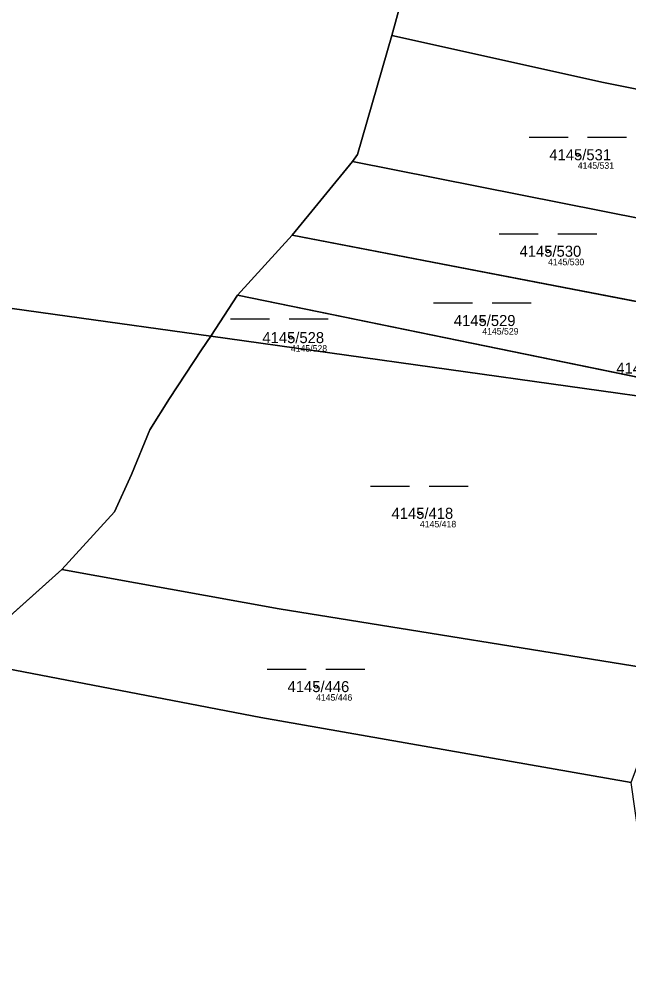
# Model space of a CAD drawing. Extents: x -739214 to -733252, y -1147612 to -1142842.
# Drawn here: x -736257.4 to -736163.6, y -1146792.7 to -1146646.4 of the extents above; entities that cross this region are included whole.
import ezdxf

# ---------------------------------------------------------------- set-up
doc = ezdxf.new("R2010")
doc.units = 0
for name, color, linetype in [('Definiční body', 7, 'Continuous'), ('Hranice parcel', 7, 'Continuous'), ('Parcelní čísla', 7, 'Continuous'), ('Polygon parcely', 7, 'Continuous'), ('Značky kultur', 7, 'Continuous')]:
    doc.layers.add(name, color=color, linetype=linetype)

msp = doc.modelspace()

# ---------------------------------------------------------------- linework, layer by layer
at = {"layer": 'Definiční body'}
for centre in [(-736171.51, -1146667.31), (-736176.09, -1146682.15), (-736186.19, -1146692.81), (-736215.61, -1146695.44), (-736195.77, -1146722.47), (-736211.74, -1146749.13)]:
    msp.add_circle(centre, 0.25, dxfattribs=at)
at = {"layer": 'Hranice parcel'}
for p, q in [((-736250, -1146692.16), (-736446.12, -1146664.77)), ((-736206.12, -1146668.34), (-736215.38, -1146679.7)), ((-736141.82, -1146681.14), (-736206.12, -1146668.34)), ((-736215.38, -1146679.7), (-736223.78, -1146688.92)), ((-736147.96, -1146692.69), (-736215.38, -1146679.7)), ((-736223.78, -1146688.92), (-736227.9, -1146695.24)), ((-736153.6, -1146703.3), (-736223.78, -1146688.92)), ((-736227.9, -1146695.24), (-736250, -1146692.16)), ((-736154.75, -1146705.46), (-736227.9, -1146695.24)), ((-736250.78, -1146731.12), (-736266.33, -1146745))]:
    msp.add_line(p, q, dxfattribs=at)
for points in [[(-736191.94, -1146599.24), (-736191.82, -1146602.51), (-736191.51, -1146612.78), (-736194.36, -1146627.44), (-736196.17, -1146634.72), (-736200.09, -1146648.96)], [(-736200.09, -1146648.96), (-736205.38, -1146667.25), (-736206.12, -1146668.34)], [(-736200.09, -1146648.96), (-736167.56, -1146656.18), (-736132.29, -1146663.24)], [(-736227.9, -1146695.24), (-736229.34, -1146697.34), (-736234.27, -1146704.81), (-736237.3, -1146709.65), (-736240.08, -1146716.48), (-736242.73, -1146722.26), (-736250.78, -1146731.12)], [(-736250.78, -1146731.12), (-736217.41, -1146737.18), (-736156.98, -1146746.9)], [(-736163.29, -1146763.86), (-736220.22, -1146753.87), (-736266.33, -1146745)]]:
    msp.add_lwpolyline(points, dxfattribs=at)
at = {"layer": 'Polygon parcely'}
for points in [[(-736446.12, -1146664.77), (-736250, -1146692.16), (-736227.9, -1146695.24), (-736223.78, -1146688.92), (-736215.38, -1146679.7), (-736206.12, -1146668.34), (-736205.38, -1146667.25), (-736200.09, -1146648.96), (-736196.17, -1146634.72), (-736194.36, -1146627.44), (-736191.51, -1146612.78), (-736191.82, -1146602.51), (-736191.94, -1146599.24), (-736191.78, -1146595.93), (-736191.97, -1146581.49), (-736191.26, -1146573.01), (-736216.79, -1146536.45)], [(-735989.23, -1146792.72), (-736114.21, -1146771.7), (-736117, -1146774.94), (-736127.17, -1146781.53), (-736150.15, -1146782.44), (-736162.08, -1146772.58), (-736163.29, -1146763.86), (-736220.22, -1146753.87), (-736266.33, -1146745)]]:
    msp.add_lwpolyline(points, dxfattribs=at)
for points in [[(-736191.51, -1146612.78), (-736194.36, -1146627.44), (-736196.17, -1146634.72), (-736200.09, -1146648.96), (-736167.56, -1146656.18), (-736132.29, -1146663.24), (-736131.9, -1146662.5), (-736122.58, -1146659.16), (-736112.56, -1146653.29), (-736102.54, -1146647.43), (-736083.6, -1146636.35), (-736081.11, -1146634.89), (-736082.04, -1146628.49), (-736082.68, -1146624.08), (-736191.94, -1146599.24), (-736191.82, -1146602.51)], [(-736206.12, -1146668.34), (-736141.82, -1146681.14), (-736132.29, -1146663.24), (-736167.56, -1146656.18), (-736200.09, -1146648.96), (-736205.38, -1146667.25)], [(-736266.33, -1146745), (-736250.78, -1146731.12), (-736242.73, -1146722.26), (-736240.08, -1146716.48), (-736237.3, -1146709.65), (-736234.27, -1146704.81), (-736229.34, -1146697.34), (-736227.9, -1146695.24), (-736250, -1146692.16), (-736446.12, -1146664.77), (-736393.74, -1146686.21), (-736368.55, -1146706.39), (-736342.55, -1146711.96), (-736320.63, -1146726.6), (-736322.44, -1146734.9), (-736298.37, -1146731.88), (-736275.71, -1146735.8)], [(-736215.38, -1146679.7), (-736147.96, -1146692.69), (-736141.82, -1146681.14), (-736206.12, -1146668.34)], [(-736147.96, -1146692.69), (-736215.38, -1146679.7), (-736223.78, -1146688.92), (-736153.6, -1146703.3)], [(-736223.78, -1146688.92), (-736227.9, -1146695.24), (-736154.75, -1146705.46), (-736153.6, -1146703.3)], [(-736242.73, -1146722.26), (-736250.78, -1146731.12), (-736217.41, -1146737.18), (-736156.98, -1146746.9), (-736156.2, -1146744.79), (-736157.02, -1146732.09), (-736157.82, -1146719.87), (-736157.9, -1146718.62), (-736156.13, -1146711.23), (-736154.75, -1146705.46), (-736227.9, -1146695.24), (-736229.34, -1146697.34), (-736234.27, -1146704.81), (-736237.3, -1146709.65), (-736240.08, -1146716.48)], [(-736266.33, -1146745), (-736220.22, -1146753.87), (-736163.29, -1146763.86), (-736156.98, -1146746.9), (-736217.41, -1146737.18), (-736250.78, -1146731.12)]]:
    msp.add_lwpolyline(points, close=True, dxfattribs=at)
at = {"layer": 'Značky kultur'}
for p, q in [((-736179, -1146664.61), (-736173, -1146664.61)), ((-736170, -1146664.61), (-736164, -1146664.61)), ((-736183.58, -1146679.45), (-736177.58, -1146679.45)), ((-736174.58, -1146679.45), (-736168.58, -1146679.45)), ((-736193.68, -1146690.11), (-736187.68, -1146690.11)), ((-736184.68, -1146690.11), (-736178.68, -1146690.11)), ((-736224.88, -1146692.54), (-736218.88, -1146692.54)), ((-736215.88, -1146692.54), (-736209.88, -1146692.54)), ((-736203.37, -1146718.29), (-736197.37, -1146718.29)), ((-736194.37, -1146718.29), (-736188.37, -1146718.29)), ((-736219.23, -1146746.43), (-736213.23, -1146746.43)), ((-736210.23, -1146746.43), (-736204.23, -1146746.43))]:
    msp.add_line(p, q, dxfattribs=at)

# ---------------------------------------------------------------- texts
at = {"layer": 'Definiční body'}
for s, p in [('4145/531', (-736171.51, -1146669.47)), ('4145/530', (-736176.09, -1146684.31)), ('4145/529', (-736186.19, -1146694.97)), ('4145/528', (-736215.61, -1146697.6)), ('4145/418', (-736195.77, -1146724.63)), ('4145/446', (-736211.74, -1146751.29))]:
    msp.add_text(s, height=1, dxfattribs=at).set_placement(p)
at = {"layer": 'Parcelní čísla'}
for s, p in [('4145/531', (-736175.88, -1146668.16)), ('4145/530', (-736180.46, -1146683)), ('4145/529', (-736190.56, -1146693.66)), ('4145/528', (-736219.98, -1146696.29)), ('4145/326', (-736165.58, -1146700.99)), ('4145/418', (-736200.14, -1146723.32)), ('4145/446', (-736216.11, -1146749.98))]:
    msp.add_text(s, height=1.7, dxfattribs=at).set_placement(p)

doc.saveas('drawing.dxf')
